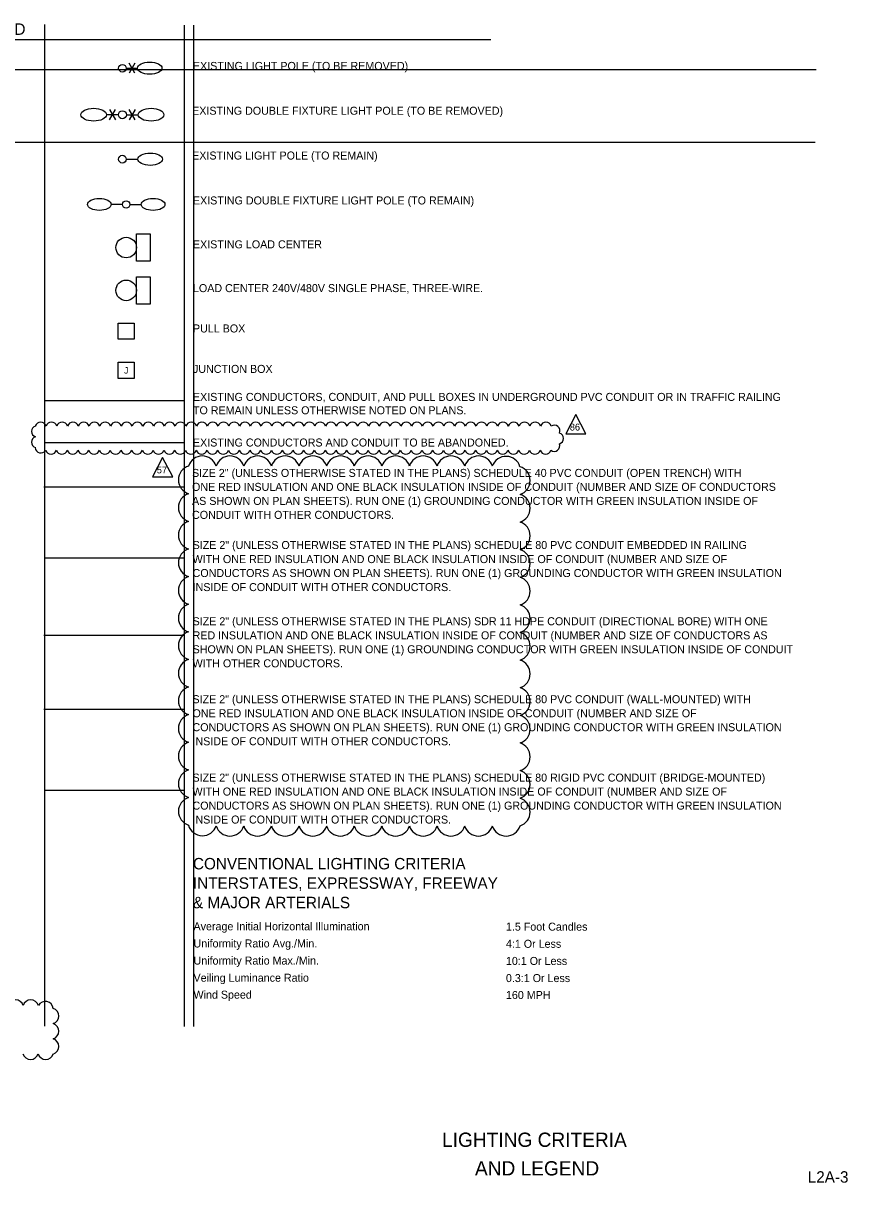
# Model space of a CAD drawing. Extents: x -0.7 to 15.2, y -0.9 to 9.6.
# Drawn here: x 7.94 to 15.15, y -0.65 to 9.5 of the extents above; entities that cross this region are included whole.
import ezdxf

# ---------------------------------------------------------------- set-up
doc = ezdxf.new("R2010")
doc.units = 0
for name, color, linetype in [('ActivePointCell_dp', 7, 'Continuous'), ('Cloud_dp', 7, 'Continuous'), ('Conduit', 7, 'Continuous'), ('JunctBoxA', 7, 'Continuous'), ('LiteCond_ep', 7, 'Continuous'), ('LoadCenter', 7, 'Continuous'), ('LoadCenter_ep', 7, 'Continuous'), ('Miscellaneous1', 7, 'Continuous'), ('Miscellaneous3', 7, 'Continuous'), ('Miscellaneous7', 7, 'Continuous'), ('Miscellaneous8', 7, 'Continuous'), ('Miscellaneous9', 7, 'Continuous'), ('PoleLight_ep', 7, 'Continuous'), ('PullBox', 7, 'Continuous'), ('TextLabel', 7, 'Continuous'), ('TextMisc', 7, 'Continuous'), ('TextNotes', 7, 'Continuous'), ('TextShtNo', 7, 'Continuous')]:
    doc.layers.add(name, color=color, linetype=linetype)

msp = doc.modelspace()

# ---------------------------------------------------------------- linework, layer by layer
at = {"layer": 'ActivePointCell_dp'}
for p, q in [((8.126, 9.487), (8.126, 0.725)), ((9.347, 9.484), (9.347, 0.722)), ((9.43, 9.484), (9.43, 0.722)), ((14.876, 9.092), (-0.655, 9.092)), ((14.867, 8.456), (-0.599, 8.456))]:
    msp.add_line(p, q, dxfattribs=at)
at = {"layer": 'Cloud_dp'}
for points in [[(12.775, 6.076), (12.687, 5.906), (12.863, 5.906)], [(9.16, 5.7), (9.072, 5.531), (9.248, 5.531)]]:
    msp.add_lwpolyline(points, close=True, dxfattribs=at)
for centre, radius, start, end in [((8.093, 5.96), 0.0493, 17.5, 162.5), ((8.187, 5.96), 0.0493, 17.5, 162.5), ((8.281, 5.96), 0.0493, 17.5, 162.5), ((8.375, 5.96), 0.0493, 17.5, 162.5), ((8.469, 5.96), 0.0493, 17.5, 162.5), ((8.563, 5.96), 0.0493, 17.5, 162.5), ((8.657, 5.96), 0.0493, 17.5, 162.5), ((8.751, 5.96), 0.0493, 17.5, 162.5), ((8.845, 5.96), 0.0493, 17.5, 162.5), ((8.939, 5.96), 0.0493, 17.5, 162.5), ((9.034, 5.96), 0.0493, 17.5, 162.5), ((9.128, 5.96), 0.0493, 17.5, 162.5), ((9.222, 5.96), 0.0493, 17.5, 162.5), ((9.316, 5.96), 0.0493, 17.5, 162.5), ((9.41, 5.96), 0.0493, 17.5, 162.5), ((9.504, 5.96), 0.0493, 17.5, 162.5), ((9.598, 5.96), 0.0493, 17.5, 162.5), ((9.692, 5.96), 0.0493, 17.5, 162.5), ((9.786, 5.96), 0.0493, 17.5, 162.5), ((9.88, 5.96), 0.0493, 17.5, 162.5), ((9.974, 5.96), 0.0493, 17.5, 162.5), ((10.068, 5.96), 0.0493, 17.5, 162.5), ((10.162, 5.96), 0.0493, 17.5, 162.5), ((10.256, 5.96), 0.0493, 17.5, 162.5), ((10.35, 5.96), 0.0493, 17.5, 162.5), ((10.444, 5.96), 0.0493, 17.5, 162.5), ((10.538, 5.96), 0.0493, 17.5, 162.5), ((10.632, 5.96), 0.0493, 17.5, 162.5), ((10.726, 5.96), 0.0493, 17.5, 162.5), ((10.82, 5.96), 0.0493, 17.5, 162.5), ((10.914, 5.96), 0.0493, 17.5, 162.5), ((11.008, 5.96), 0.0493, 17.5, 162.5), ((11.102, 5.96), 0.0493, 17.5, 162.5), ((11.197, 5.96), 0.0493, 17.5, 162.5), ((11.291, 5.96), 0.0493, 17.5, 162.5), ((11.385, 5.96), 0.0493, 17.5, 162.5), ((11.479, 5.96), 0.0493, 17.5, 162.5), ((11.573, 5.96), 0.0493, 17.5, 162.5), ((11.667, 5.96), 0.0493, 17.5, 162.5), ((11.761, 5.96), 0.0493, 17.5, 162.5), ((11.855, 5.96), 0.0493, 17.5, 162.5), ((11.949, 5.96), 0.0493, 17.5, 162.5), ((12.043, 5.96), 0.0493, 17.5, 162.5), ((12.137, 5.96), 0.0493, 17.5, 162.5), ((12.231, 5.96), 0.0493, 17.5, 162.5), ((12.325, 5.96), 0.0493, 17.5, 162.5), ((12.419, 5.96), 0.0493, 17.5, 162.5), ((12.513, 5.96), 0.0493, 17.5, 162.5), ((8.061, 5.928), 0.0493, 107.5, 252.5), ((12.586, 5.933), 0.0493, 337.1323, 122.1323), ((12.617, 5.867), 0.0493, 287.5, 72.5), ((8.061, 5.834), 0.0493, 107.5, 252.5), ((8.095, 5.789), 0.0493, 182.728, 327.728), ((12.585, 5.803), 0.0493, 234.913, 19.913), ((8.184, 5.778), 0.0493, 197.5, 342.5), ((8.278, 5.778), 0.0493, 197.5, 342.5), ((8.372, 5.778), 0.0493, 197.5, 342.5), ((8.466, 5.778), 0.0493, 197.5, 342.5), ((8.56, 5.778), 0.0493, 197.5, 342.5), ((8.654, 5.778), 0.0493, 197.5, 342.5), ((8.748, 5.778), 0.0493, 197.5, 342.5), ((8.842, 5.778), 0.0493, 197.5, 342.5), ((8.936, 5.778), 0.0493, 197.5, 342.5), ((9.03, 5.778), 0.0493, 197.5, 342.5), ((9.124, 5.778), 0.0493, 197.5, 342.5), ((9.219, 5.778), 0.0493, 197.5, 342.5), ((9.313, 5.778), 0.0493, 197.5, 342.5), ((9.407, 5.778), 0.0493, 197.5, 342.5), ((9.507, 5.586), 0.127, 17.5, 162.5), ((9.501, 5.778), 0.0493, 197.5, 342.5), ((9.595, 5.778), 0.0493, 197.5, 342.5), ((9.749, 5.586), 0.127, 17.5, 162.5), ((9.689, 5.778), 0.0493, 197.5, 342.5), ((9.783, 5.778), 0.0493, 197.5, 342.5), ((9.877, 5.778), 0.0493, 197.5, 342.5), ((9.991, 5.586), 0.127, 17.5, 162.5), ((9.971, 5.778), 0.0493, 197.5, 342.5), ((10.065, 5.778), 0.0493, 197.5, 342.5), ((10.232, 5.586), 0.127, 17.5, 162.5), ((10.159, 5.778), 0.0493, 197.5, 342.5), ((10.253, 5.778), 0.0493, 197.5, 342.5), ((10.347, 5.778), 0.0493, 197.5, 342.5), ((10.474, 5.586), 0.127, 17.5, 162.5), ((10.441, 5.778), 0.0493, 197.5, 342.5), ((10.535, 5.778), 0.0493, 197.5, 342.5), ((10.629, 5.778), 0.0493, 197.5, 342.5), ((10.715, 5.586), 0.127, 17.5, 162.5), ((10.723, 5.778), 0.0493, 197.5, 342.5), ((10.817, 5.778), 0.0493, 197.5, 342.5), ((10.957, 5.586), 0.127, 17.5, 162.5), ((10.911, 5.778), 0.0493, 197.5, 342.5), ((11.005, 5.778), 0.0493, 197.5, 342.5), ((11.099, 5.778), 0.0493, 197.5, 342.5), ((11.199, 5.586), 0.127, 17.5, 162.5), ((11.193, 5.778), 0.0493, 197.5, 342.5), ((11.287, 5.778), 0.0493, 197.5, 342.5), ((11.44, 5.586), 0.127, 17.5, 162.5), ((11.381, 5.778), 0.0493, 197.5, 342.5), ((11.476, 5.778), 0.0493, 197.5, 342.5), ((11.57, 5.778), 0.0493, 197.5, 342.5), ((11.682, 5.586), 0.127, 17.5, 162.5), ((11.664, 5.778), 0.0493, 197.5, 342.5), ((11.758, 5.778), 0.0493, 197.5, 342.5), ((11.924, 5.586), 0.127, 17.5, 162.5), ((11.852, 5.778), 0.0493, 197.5, 342.5), ((11.946, 5.778), 0.0493, 197.5, 342.5), ((12.04, 5.778), 0.0493, 197.5, 342.5), ((12.164, 5.583), 0.127, 16.1194, 161.1194), ((12.134, 5.778), 0.0493, 197.5, 342.5), ((12.228, 5.778), 0.0493, 197.5, 342.5), ((12.322, 5.778), 0.0493, 197.5, 342.5), ((12.416, 5.778), 0.0493, 197.5, 342.5), ((12.51, 5.778), 0.0493, 197.5, 342.5), ((9.425, 5.504), 0.127, 107.5, 252.5), ((12.248, 5.498), 0.127, 287.5, 72.5), ((9.425, 5.262), 0.127, 107.5, 252.5), ((12.248, 5.256), 0.127, 287.5, 72.5), ((9.425, 5.02), 0.127, 107.5, 252.5), ((12.248, 5.014), 0.127, 287.5, 72.5), ((9.425, 4.779), 0.127, 107.5, 252.5), ((12.248, 4.773), 0.127, 287.5, 72.5), ((9.425, 4.537), 0.127, 107.5, 252.5), ((12.248, 4.531), 0.127, 287.5, 72.5), ((9.425, 4.295), 0.127, 107.5, 252.5), ((12.248, 4.29), 0.127, 287.5, 72.5), ((9.425, 4.054), 0.127, 107.5, 252.5), ((12.248, 4.048), 0.127, 287.5, 72.5), ((9.425, 3.812), 0.127, 107.5, 252.5), ((12.248, 3.806), 0.127, 287.5, 72.5), ((9.425, 3.571), 0.127, 107.5, 252.5), ((12.248, 3.565), 0.127, 287.5, 72.5), ((9.425, 3.329), 0.127, 107.5, 252.5), ((12.248, 3.323), 0.127, 287.5, 72.5), ((9.425, 3.087), 0.127, 107.5, 252.5), ((12.248, 3.081), 0.127, 287.5, 72.5), ((9.425, 2.846), 0.127, 107.5, 252.5), ((12.248, 2.84), 0.127, 287.5, 72.5), ((9.425, 2.604), 0.127, 107.5, 252.5), ((12.248, 2.598), 0.127, 287.5, 72.5), ((9.508, 2.518), 0.127, 196.1194, 341.1194), ((9.749, 2.515), 0.127, 197.5, 342.5), ((9.99, 2.515), 0.127, 197.5, 342.5), ((10.232, 2.515), 0.127, 197.5, 342.5), ((10.474, 2.515), 0.127, 197.5, 342.5), ((10.715, 2.515), 0.127, 197.5, 342.5), ((10.957, 2.515), 0.127, 197.5, 342.5), ((11.198, 2.515), 0.127, 197.5, 342.5), ((11.44, 2.515), 0.127, 197.5, 342.5), ((11.682, 2.515), 0.127, 197.5, 342.5), ((11.923, 2.515), 0.127, 197.5, 342.5), ((12.165, 2.515), 0.127, 197.5, 342.5), ((7.873, 0.885), 0.0697, 17.5, 162.5), ((8.006, 0.885), 0.0697, 17.5, 162.5), ((8.134, 0.872), 0.0696, 5.9405, 150.9405), ((8.182, 0.813), 0.0697, 287.5, 72.5), ((8.182, 0.68), 0.0697, 287.5, 72.5), ((8.182, 0.547), 0.0697, 287.5, 72.5), ((8.004, 0.502), 0.0697, 197.5, 342.5), ((8.137, 0.502), 0.0697, 197.5, 342.5)]:
    msp.add_arc(centre, radius, start, end, dxfattribs=at)
at = {"layer": 'Conduit'}
msp.add_line((8.126, 6.199), (9.347, 6.199), dxfattribs=at)
at = {"layer": 'LiteCond_ep'}
msp.add_line((8.126, 5.831), (9.347, 5.831), dxfattribs=at)
at = {"layer": 'LoadCenter'}
for p, q in [((8.931, 7.042), (8.931, 7.282)), ((8.931, 7.282), (9.051, 7.282)), ((9.051, 7.282), (9.051, 7.042)), ((9.051, 7.042), (8.931, 7.042))]:
    msp.add_line(p, q, dxfattribs=at)
msp.add_circle((8.841, 7.162), 0.09, dxfattribs=at)
at = {"layer": 'LoadCenter_ep'}
for p, q in [((8.931, 7.417), (8.931, 7.657)), ((8.931, 7.657), (9.051, 7.657)), ((9.051, 7.657), (9.051, 7.417)), ((9.051, 7.417), (8.931, 7.417))]:
    msp.add_line(p, q, dxfattribs=at)
msp.add_circle((8.841, 7.537), 0.09, dxfattribs=at)
at = {"layer": 'Miscellaneous1'}
msp.add_line((8.121, 5.443), (9.343, 5.443), dxfattribs=at)
at = {"layer": 'Miscellaneous3'}
msp.add_line((8.121, 4.145), (9.343, 4.145), dxfattribs=at)
at = {"layer": 'Miscellaneous7'}
msp.add_line((8.125, 4.821), (9.343, 4.821), dxfattribs=at)
at = {"layer": 'Miscellaneous8'}
msp.add_line((8.121, 3.499), (9.342, 3.499), dxfattribs=at)
at = {"layer": 'Miscellaneous9'}
msp.add_line((8.122, 2.79), (9.344, 2.79), dxfattribs=at)
at = {"layer": 'PoleLight_ep'}
for p, q in [((8.916, 9.063), (8.866, 9.149)), ((8.916, 9.149), (8.866, 9.063)), ((8.841, 9.106), (8.941, 9.106)), ((8.695, 8.653), (8.748, 8.744)), ((8.695, 8.744), (8.748, 8.653)), ((8.92, 8.745), (8.868, 8.654)), ((8.92, 8.654), (8.868, 8.745)), ((8.773, 8.699), (8.668, 8.699)), ((8.843, 8.699), (8.947, 8.699)), ((8.841, 8.31), (8.943, 8.31)), ((8.808, 7.914), (8.71, 7.914)), ((8.873, 7.914), (8.971, 7.914))]:
    msp.add_line(p, q, dxfattribs=at)
for centre, radius in [((8.808, 9.106), 0.0333), ((8.808, 8.699), 0.0349), ((8.808, 8.31), 0.0338), ((8.841, 7.914), 0.0326)]:
    msp.add_circle(centre, radius, dxfattribs=at)
for centre, major_axis in [((9.047, 9.106), (0.107, 0)), ((8.556, 8.699), (-0.112, 0)), ((9.059, 8.699), (0.112, 0)), ((9.051, 8.31), (0.108, 0)), ((8.606, 7.914), (-0.104, 0)), ((9.076, 7.914), (0.104, 0))]:
    msp.add_ellipse(centre, major_axis=major_axis, ratio=0.5, dxfattribs=at)
at = {"layer": 'PullBox'}
for p, q in [((8.77, 6.734), (8.77, 6.875)), ((8.77, 6.875), (8.911, 6.875)), ((8.911, 6.875), (8.911, 6.734)), ((8.911, 6.734), (8.77, 6.734)), ((8.77, 6.533), (8.911, 6.533)), ((8.77, 6.392), (8.77, 6.533)), ((8.911, 6.533), (8.911, 6.392)), ((8.911, 6.392), (8.77, 6.392))]:
    msp.add_line(p, q, dxfattribs=at)
at = {"layer": 'TextLabel'}
msp.add_line((3.976, 9.358), (12.03, 9.358), dxfattribs=at)

# ---------------------------------------------------------------- texts
at = {"layer": 'Cloud_dp'}
for s, p in [('86', (12.722, 5.936)), ('57', (9.109, 5.561))]:
    msp.add_text(s, height=0.06, dxfattribs=at).set_placement(p)
at = {"layer": 'JunctBoxA'}
msp.add_text('J', height=0.0563, dxfattribs=at).set_placement((8.822, 6.434))
at = {"layer": 'TextLabel'}
for s, p in [('CONVENTIONAL LIGHTING CRITERIA', (9.425, 2.096)), ('INTERSTATES, EXPRESSWAY, FREEWAY', (9.425, 1.926)), ('& MAJOR ARTERIALS', (9.425, 1.756))]:
    msp.add_text(s, height=0.1, dxfattribs=at).set_placement(p)
at = {"layer": 'TextMisc'}
for s, height, p in [('LEGEND', 0.1, (7.41, 9.398)), ('   LIGHTING CRITERIA    ', 0.125, (11.465, -0.332)), ('       AND LEGEND       ', 0.125, (11.567, -0.582))]:
    msp.add_text(s, height=height, dxfattribs=at).set_placement(p)
for s, p in [('EXISTING LIGHT POLE (TO BE REMOVED)', (9.425, 9.091)), ('EXISTING DOUBLE FIXTURE LIGHT POLE (TO BE REMOVED)', (9.418, 8.699)), ('EXISTING LIGHT POLE (TO REMAIN)', (9.418, 8.307)), ('EXISTING DOUBLE FIXTURE LIGHT POLE (TO REMAIN)', (9.425, 7.914)), ('EXISTING LOAD CENTER', (9.425, 7.53)), ('LOAD CENTER 240V/480V SINGLE PHASE, THREE-WIRE.', (9.425, 7.147)), ('PULL BOX', (9.425, 6.794)), ('JUNCTION BOX', (9.425, 6.44)), ('EXISTING CONDUCTORS, CONDUIT, AND PULL BOXES IN UNDERGROUND PVC CONDUIT OR IN TRAFFIC RAILING ', (9.425, 6.195)), ('TO REMAIN UNLESS OTHERWISE NOTED ON PLANS.', (9.425, 6.078)), ('EXISTING CONDUCTORS AND CONDUIT TO BE ABANDONED.', (9.425, 5.796)), ('SIZE 2" (UNLESS OTHERWISE STATED IN THE PLANS) SCHEDULE 40 PVC CONDUIT (OPEN TRENCH) WITH ', (9.417, 5.53)), ('ONE RED INSULATION AND ONE BLACK INSULATION INSIDE OF CONDUIT (NUMBER AND SIZE OF CONDUCTORS ', (9.417, 5.408)), ('AS SHOWN ON PLAN SHEETS). RUN ONE (1) GROUNDING CONDUCTOR WITH GREEN INSULATION INSIDE OF ', (9.417, 5.285)), ('CONDUIT WITH OTHER CONDUCTORS.', (9.417, 5.163)), ('SIZE 2" (UNLESS OTHERWISE STATED IN THE PLANS) SCHEDULE 80 PVC CONDUIT EMBEDDED IN RAILING ', (9.422, 4.899)), ('WITH ONE RED INSULATION AND ONE BLACK INSULATION INSIDE OF CONDUIT (NUMBER AND SIZE OF ', (9.422, 4.776)), ('CONDUCTORS AS SHOWN ON PLAN SHEETS). RUN ONE (1) GROUNDING CONDUCTOR WITH GREEN INSULATION ', (9.422, 4.654)), ('INSIDE OF CONDUIT WITH OTHER CONDUCTORS.', (9.422, 4.531)), ('SIZE 2" (UNLESS OTHERWISE STATED IN THE PLANS) SDR 11 HDPE CONDUIT (DIRECTIONAL BORE) WITH ONE ', (9.422, 4.232)), ('RED INSULATION AND ONE BLACK INSULATION INSIDE OF CONDUIT (NUMBER AND SIZE OF CONDUCTORS AS ', (9.422, 4.109)), ('SHOWN ON PLAN SHEETS). RUN ONE (1) GROUNDING CONDUCTOR WITH GREEN INSULATION INSIDE OF CONDUIT ', (9.422, 3.987)), ('WITH OTHER CONDUCTORS.', (9.422, 3.864)), ('SIZE 2" (UNLESS OTHERWISE STATED IN THE PLANS) SCHEDULE 80 PVC CONDUIT (WALL-MOUNTED) WITH ', (9.421, 3.55)), ('ONE RED INSULATION AND ONE BLACK INSULATION INSIDE OF CONDUIT (NUMBER AND SIZE OF ', (9.421, 3.427)), ('CONDUCTORS AS SHOWN ON PLAN SHEETS). RUN ONE (1) GROUNDING CONDUCTOR WITH GREEN INSULATION ', (9.421, 3.305)), ('INSIDE OF CONDUIT WITH OTHER CONDUCTORS.', (9.421, 3.182)), ('SIZE 2" (UNLESS OTHERWISE STATED IN THE PLANS) SCHEDULE 80 RIGID PVC CONDUIT (BRIDGE-MOUNTED) ', (9.421, 2.864)), ('WITH ONE RED INSULATION AND ONE BLACK INSULATION INSIDE OF CONDUIT (NUMBER AND SIZE OF ', (9.421, 2.742)), ('CONDUCTORS AS SHOWN ON PLAN SHEETS). RUN ONE (1) GROUNDING CONDUCTOR WITH GREEN INSULATION ', (9.421, 2.619)), ('INSIDE OF CONDUIT WITH OTHER CONDUCTORS.', (9.421, 2.497))]:
    msp.add_text(s, height=0.07, rotation=360, dxfattribs=at).set_placement(p)
at = {"layer": 'TextNotes'}
for s, p in [('Average Initial Horizontal Illumination', (9.43, 1.563)), ('1.5 Foot Candles', (12.163, 1.56)), ('Uniformity Ratio Avg./Min.', (9.43, 1.413)), ('4:1 Or Less', (12.163, 1.41)), ('Uniformity Ratio Max./Min.', (9.43, 1.263)), ('10:1 Or Less', (12.163, 1.26)), ('Veiling Luminance Ratio', (9.43, 1.113)), ('0.3:1 Or Less', (12.163, 1.11)), ('Wind Speed', (9.43, 0.965)), ('160 MPH', (12.163, 0.962))]:
    msp.add_text(s, height=0.07, dxfattribs=at).set_placement(p)
at = {"layer": 'TextShtNo'}
msp.add_text('L2A-3 ', height=0.1, rotation=360, dxfattribs=at).set_placement((14.803, -0.645))

doc.saveas('drawing.dxf')
